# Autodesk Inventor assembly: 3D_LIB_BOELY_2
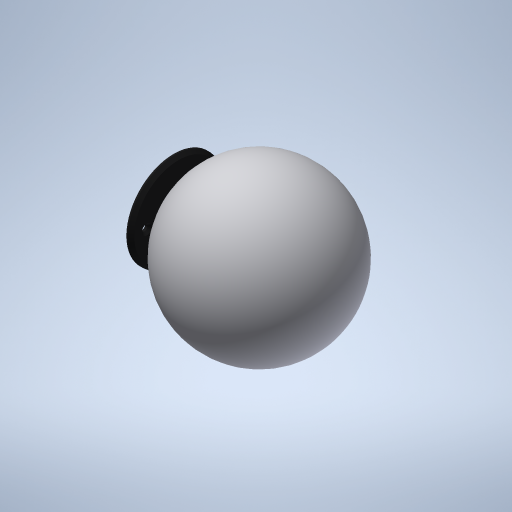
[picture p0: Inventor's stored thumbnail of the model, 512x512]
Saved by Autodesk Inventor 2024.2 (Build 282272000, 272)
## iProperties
Created: 2024-05
Part Number: 3D_LIB_BOELY_2
Project: 452 - BOELY
Description: BOELY Wood - Assy
Document SubType Name: Assembly
Designer: Manuel
Manager: Filip
Company: DARK
Author: Manuel
Revision Number: v0
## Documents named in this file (7)
- C:\Users\Stage\Desktop\Stage Karsten\armatures\452 - BOELY\452_KARSTEN\3D_LIB_BOELY_2.iam
- N:\LIBRARY\FITTINGEN\BJB 25.834_G9.ipt
- N:\LIBRARY\FITTINGEN\BJB 25.934_for G9.ipt
- N:\LIBRARY\BEVESTIGING\Draadstang-trompetnipple\Draadstang M10x1 L16.ipt
- C:\Users\Stage\Desktop\Stage Karsten\armatures\452 - BOELY\Glass Sphere Dia.100mm.ipt
- N:\LIBRARY\LAMPEN\LED\G9-6W-2700K-CRI 90.ipt
- C:\Users\Stage\Desktop\Stage Karsten\armatures\452 - BOELY\452-002.ipt
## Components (6 placed, 6 different names)
1. BJB 25.834_G9:1 — Mate:5, Mate:6, Angle:3, Mate:14, Mate:15, Mate:17
2. BJB 25.934_for G9:1 — Angle:1, Mate:3, Mate:4, Mate:5, Mate:6, Mate:17, Mate:18, Mate:19, Angle:4, Mate:20
3. Draadstang M10x1 L16:1 — Angle:1, Mate:3, Mate:4
4. Glass Sphere Dia.100mm:1 — Angle:4, Mate:20
5. G9-6W-2700K-CRI 90:1 — Angle:3, Mate:14, Mate:15
6. 452-002:1 — Flush:1, Flush:2, Flush:3, Mate:18, Mate:19
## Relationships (16: Mate 10, Angle 3, Flush 3)
- Angle:1: BJB 25.934_for G9:1 ↔ Draadstang M10x1 L16:1
- Mate:3: BJB 25.934_for G9:1 ↔ Draadstang M10x1 L16:1
- Mate:4: BJB 25.934_for G9:1 ↔ Draadstang M10x1 L16:1
- Mate:5: BJB 25.834_G9:1 ↔ BJB 25.934_for G9:1
- Mate:6: BJB 25.834_G9:1 ↔ BJB 25.934_for G9:1
- Angle:3: BJB 25.834_G9:1 ↔ G9-6W-2700K-CRI 90:1
- Mate:14: BJB 25.834_G9:1 ↔ G9-6W-2700K-CRI 90:1
- Mate:15: BJB 25.834_G9:1 ↔ G9-6W-2700K-CRI 90:1
- Mate:17: BJB 25.834_G9:1 ↔ BJB 25.934_for G9:1
- Flush:1: 452-002:1
- Flush:2: 452-002:1
- Flush:3: 452-002:1
- Mate:18: BJB 25.934_for G9:1 ↔ 452-002:1
- Mate:19: BJB 25.934_for G9:1 ↔ 452-002:1
- Angle:4: BJB 25.934_for G9:1 ↔ Glass Sphere Dia.100mm:1
- Mate:20: BJB 25.934_for G9:1 ↔ Glass Sphere Dia.100mm:1
